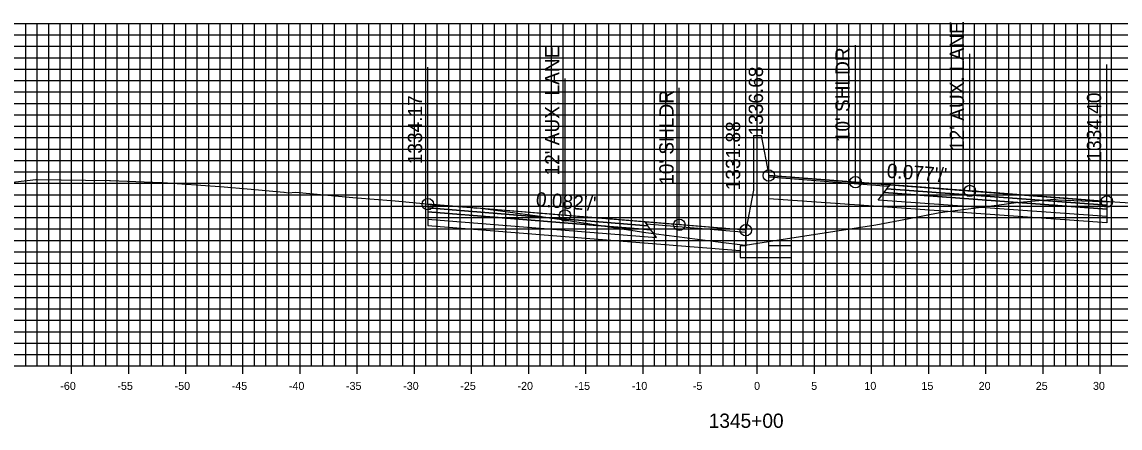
# Model space of a CAD drawing. Extents: x 674939 to 678919, y 750652 to 765176.
# Drawn here: x 678674.2 to 678770.3, y 753062.1 to 753097.7 of the extents above; entities that cross this region are included whole.
import ezdxf

# ---------------------------------------------------------------- set-up
doc = ezdxf.new("R2010")
doc.units = 0
for name, color, linetype in [('R_Alt Surface', 7, 'Continuous'), ('R_Axis', 7, 'Continuous'), ('R_Axis Annot', 7, 'Continuous'), ('R_Exist Surface', 7, 'Continuous'), ('R_Fin Surface', 7, 'Continuous'), ('R_Grid', 7, 'Continuous'), ('R_No Plot', 7, 'Continuous'), ('R_Proposed Road', 7, 'Continuous'), ('R_Xsect Elev', 7, 'Continuous'), ('R_Xsect Slope', 7, 'Continuous')]:
    doc.layers.add(name, color=color, linetype=linetype)

msp = doc.modelspace()

# ---------------------------------------------------------------- linework, layer by layer
at = {"layer": 'R_Alt Surface'}
for points in [[(678769.12, 753081.295), (678769.12, 753080.635), (678749.12, 753082.057), (678749.62, 753082.737)], [(678769.12, 753081.625), (678769.12, 753081.295), (678749.62, 753082.737), (678749.87, 753083.077)], [(678709.709, 753081.386), (678709.709, 753081.056), (678729.209, 753079.478), (678728.959, 753079.818)], [(678709.709, 753081.056), (678709.709, 753080.396), (678729.709, 753078.798), (678729.209, 753079.478)]]:
    msp.add_lwpolyline(points, close=True, dxfattribs=at)
for points in [[(678749.12, 753081.517), (678739.533, 753082.199)], [(678769.12, 753080.635), (678769.121, 753080.095), (678749.12, 753081.517)], [(678709.709, 753080.396), (678709.709, 753079.856), (678729.709, 753078.258)], [(678729.709, 753078.258), (678737.033, 753077.673)]]:
    msp.add_lwpolyline(points, dxfattribs=at)
at = {"layer": 'R_Axis'}
for p, q in [((678678.533, 753066.851), (678678.533, 753068.251)), ((678683.533, 753066.851), (678683.533, 753068.251)), ((678688.533, 753066.851), (678688.533, 753068.251)), ((678693.533, 753066.851), (678693.533, 753068.251)), ((678698.533, 753066.851), (678698.533, 753068.251)), ((678703.533, 753066.851), (678703.533, 753068.251)), ((678708.533, 753066.851), (678708.533, 753068.251)), ((678713.533, 753066.851), (678713.533, 753068.251)), ((678718.533, 753066.851), (678718.533, 753068.251)), ((678723.533, 753066.851), (678723.533, 753068.251)), ((678728.533, 753066.851), (678728.533, 753068.251)), ((678733.533, 753066.851), (678733.533, 753068.251)), ((678738.533, 753066.851), (678738.533, 753068.251)), ((678743.533, 753066.851), (678743.533, 753068.251)), ((678748.533, 753066.851), (678748.533, 753068.251)), ((678753.533, 753066.851), (678753.533, 753068.251)), ((678758.533, 753066.851), (678758.533, 753068.251)), ((678763.533, 753066.851), (678763.533, 753068.251)), ((678768.533, 753066.851), (678768.533, 753068.251)), ((678638.533, 753067.551), (678838.533, 753067.551))]:
    msp.add_line(p, q, dxfattribs=at)
at = {"layer": 'R_Exist Surface'}
msp.add_lwpolyline([(678671.826, 753083.464), (678675.401, 753083.866), (678675.405, 753083.866), (678675.531, 753083.889), (678681.853, 753083.782), (678681.941, 753083.78), (678686.361, 753083.629), (678686.385, 753083.628), (678686.388, 753083.628), (678686.528, 753083.623), (678691.513, 753083.259), (678691.533, 753083.257), (678694.246, 753083.023), (678697.12, 753082.775), (678697.127, 753082.774), (678697.526, 753082.726), (678697.529, 753082.726), (678698.127, 753082.758), (678703.476, 753082.287), (678703.53, 753082.282), (678706.492, 753082.053), (678706.549, 753082.048), (678709.31, 753081.772), (678709.331, 753081.769), (678709.709, 753081.716), (678709.719, 753081.715), (678710.129, 753081.657), (678710.145, 753081.656), (678711.522, 753081.589), (678711.536, 753081.588), (678711.558, 753081.586), (678713.521, 753081.423), (678713.529, 753081.422), (678713.537, 753081.423), (678713.929, 753081.381), (678714.102, 753081.391), (678719.311, 753080.687), (678720.158, 753080.566), (678721.432, 753080.385), (678728.77, 753079.23), (678735.104, 753078.424), (678737.458, 753078.123), (678740.612, 753078.616), (678748.891, 753079.903), (678751.665, 753080.424), (678754.489, 753080.979), (678759.688, 753081.672), (678761.175, 753081.869), (678761.818, 753081.933), (678764.548, 753082.16), (678764.632, 753082.143), (678764.865, 753082.099), (678765.532, 753082.077), (678766.931, 753082.025), (678767.851, 753081.978), (678768.433, 753081.942), (678768.871, 753081.949), (678769.12, 753081.955), (678769.262, 753081.958), (678769.349, 753081.96), (678771.62, 753081.795)], dxfattribs=at)
at = {"layer": 'R_Fin Surface'}
for points in [[(678769.12, 753081.955), (678757.12, 753082.878), (678747.12, 753083.648), (678739.533, 753084.232)], [(678737.533, 753079.435), (678731.709, 753079.913), (678721.709, 753080.732), (678709.709, 753081.716)]]:
    msp.add_lwpolyline(points, dxfattribs=at)
for points in [[(678750.002, 753083.257), (678739.533, 753084.072), (678739.533, 753084.232), (678750.12, 753083.417)], [(678769.12, 753081.955), (678769.12, 753081.625), (678749.87, 753083.077), (678750.12, 753083.417)], [(678709.709, 753081.716), (678709.709, 753081.386), (678728.959, 753079.818), (678728.709, 753080.158)], [(678728.827, 753079.998), (678737.533, 753079.275), (678737.533, 753079.435), (678728.709, 753080.158)]]:
    msp.add_lwpolyline(points, close=True, dxfattribs=at)
at = {"layer": 'R_Grid'}
for p, q in [((678638.533, 753097.551), (678838.533, 753097.551)), ((678674.533, 753067.551), (678674.533, 753097.551)), ((678675.533, 753067.551), (678675.533, 753097.551)), ((678676.533, 753067.551), (678676.533, 753097.551)), ((678677.533, 753067.551), (678677.533, 753097.551)), ((678678.533, 753067.551), (678678.533, 753097.551)), ((678679.533, 753067.551), (678679.533, 753097.551)), ((678680.533, 753067.551), (678680.533, 753097.551)), ((678681.533, 753067.551), (678681.533, 753097.551)), ((678682.533, 753067.551), (678682.533, 753097.551)), ((678683.533, 753067.551), (678683.533, 753097.551)), ((678684.533, 753067.551), (678684.533, 753097.551)), ((678685.533, 753067.551), (678685.533, 753097.551)), ((678686.533, 753067.551), (678686.533, 753097.551)), ((678687.533, 753067.551), (678687.533, 753097.551)), ((678688.533, 753067.551), (678688.533, 753097.551)), ((678689.533, 753067.551), (678689.533, 753097.551)), ((678690.533, 753067.551), (678690.533, 753097.551)), ((678691.533, 753067.551), (678691.533, 753097.551)), ((678692.533, 753067.551), (678692.533, 753097.551)), ((678693.533, 753067.551), (678693.533, 753097.551)), ((678694.533, 753067.551), (678694.533, 753097.551)), ((678695.533, 753067.551), (678695.533, 753097.551)), ((678696.533, 753067.551), (678696.533, 753097.551)), ((678697.533, 753067.551), (678697.533, 753097.551)), ((678698.533, 753067.551), (678698.533, 753097.551)), ((678699.533, 753067.551), (678699.533, 753097.551)), ((678700.533, 753067.551), (678700.533, 753097.551)), ((678701.533, 753067.551), (678701.533, 753097.551)), ((678702.533, 753067.551), (678702.533, 753097.551)), ((678703.533, 753067.551), (678703.533, 753097.551)), ((678704.533, 753067.551), (678704.533, 753097.551)), ((678705.533, 753067.551), (678705.533, 753097.551)), ((678706.533, 753067.551), (678706.533, 753097.551)), ((678707.533, 753067.551), (678707.533, 753097.551)), ((678708.533, 753067.551), (678708.533, 753097.551)), ((678709.533, 753067.551), (678709.533, 753097.551)), ((678710.533, 753067.551), (678710.533, 753097.551)), ((678711.533, 753067.551), (678711.533, 753097.551)), ((678712.533, 753067.551), (678712.533, 753097.551)), ((678713.533, 753067.551), (678713.533, 753097.551)), ((678714.533, 753067.551), (678714.533, 753097.551)), ((678715.533, 753067.551), (678715.533, 753097.551)), ((678716.533, 753067.551), (678716.533, 753097.551)), ((678717.533, 753067.551), (678717.533, 753097.551)), ((678718.533, 753067.551), (678718.533, 753097.551)), ((678719.533, 753067.551), (678719.533, 753097.551)), ((678720.533, 753067.551), (678720.533, 753097.551)), ((678721.533, 753067.551), (678721.533, 753097.551)), ((678722.533, 753067.551), (678722.533, 753097.551)), ((678723.533, 753067.551), (678723.533, 753097.551)), ((678724.533, 753067.551), (678724.533, 753097.551)), ((678725.533, 753067.551), (678725.533, 753097.551)), ((678726.533, 753067.551), (678726.533, 753097.551)), ((678727.533, 753067.551), (678727.533, 753097.551)), ((678728.533, 753067.551), (678728.533, 753097.551)), ((678729.533, 753067.551), (678729.533, 753097.551)), ((678730.533, 753067.551), (678730.533, 753097.551)), ((678731.533, 753067.551), (678731.533, 753097.551)), ((678732.533, 753067.551), (678732.533, 753097.551)), ((678733.533, 753067.551), (678733.533, 753097.551)), ((678734.533, 753067.551), (678734.533, 753097.551)), ((678735.533, 753067.551), (678735.533, 753097.551)), ((678736.533, 753067.551), (678736.533, 753097.551)), ((678737.533, 753067.551), (678737.533, 753097.551)), ((678738.533, 753067.551), (678738.533, 753097.551)), ((678739.533, 753067.551), (678739.533, 753097.551)), ((678740.533, 753067.551), (678740.533, 753097.551)), ((678741.533, 753067.551), (678741.533, 753097.551)), ((678742.533, 753067.551), (678742.533, 753097.551)), ((678743.533, 753067.551), (678743.533, 753097.551)), ((678744.533, 753067.551), (678744.533, 753097.551)), ((678745.533, 753067.551), (678745.533, 753097.551)), ((678746.533, 753067.551), (678746.533, 753097.551)), ((678747.533, 753067.551), (678747.533, 753097.551)), ((678748.533, 753067.551), (678748.533, 753097.551)), ((678749.533, 753067.551), (678749.533, 753097.551)), ((678750.533, 753067.551), (678750.533, 753097.551)), ((678751.533, 753067.551), (678751.533, 753097.551)), ((678752.533, 753067.551), (678752.533, 753097.551)), ((678753.533, 753067.551), (678753.533, 753097.551)), ((678754.533, 753067.551), (678754.533, 753097.551)), ((678755.533, 753067.551), (678755.533, 753097.551)), ((678756.533, 753067.551), (678756.533, 753097.551)), ((678757.533, 753067.551), (678757.533, 753097.551)), ((678758.533, 753067.551), (678758.533, 753097.551)), ((678759.533, 753067.551), (678759.533, 753097.551)), ((678760.533, 753067.551), (678760.533, 753097.551)), ((678761.533, 753067.551), (678761.533, 753097.551)), ((678762.533, 753067.551), (678762.533, 753097.551)), ((678763.533, 753067.551), (678763.533, 753097.551)), ((678764.533, 753067.551), (678764.533, 753097.551)), ((678765.533, 753067.551), (678765.533, 753097.551)), ((678766.533, 753067.551), (678766.533, 753097.551)), ((678767.533, 753067.551), (678767.533, 753097.551)), ((678768.533, 753067.551), (678768.533, 753097.551)), ((678769.533, 753067.551), (678769.533, 753097.551)), ((678638.533, 753096.551), (678838.533, 753096.551)), ((678638.533, 753095.551), (678838.533, 753095.551)), ((678638.533, 753094.551), (678838.533, 753094.551)), ((678638.533, 753093.551), (678838.533, 753093.551)), ((678638.533, 753092.551), (678838.533, 753092.551)), ((678638.533, 753091.551), (678838.533, 753091.551)), ((678638.533, 753090.551), (678838.533, 753090.551)), ((678638.533, 753089.551), (678838.533, 753089.551)), ((678638.533, 753088.551), (678838.533, 753088.551)), ((678638.533, 753087.551), (678838.533, 753087.551)), ((678638.533, 753086.551), (678838.533, 753086.551)), ((678638.533, 753085.551), (678838.533, 753085.551)), ((678638.533, 753084.551), (678838.533, 753084.551)), ((678638.533, 753083.551), (678838.533, 753083.551)), ((678638.533, 753082.551), (678838.533, 753082.551)), ((678638.533, 753081.551), (678838.533, 753081.551)), ((678638.533, 753080.551), (678838.533, 753080.551)), ((678638.533, 753079.551), (678838.533, 753079.551)), ((678638.533, 753078.551), (678838.533, 753078.551)), ((678638.533, 753077.551), (678838.533, 753077.551)), ((678638.533, 753076.551), (678838.533, 753076.551)), ((678638.533, 753075.551), (678838.533, 753075.551)), ((678638.533, 753074.551), (678838.533, 753074.551)), ((678638.533, 753073.551), (678838.533, 753073.551)), ((678638.533, 753072.551), (678838.533, 753072.551)), ((678638.533, 753071.551), (678838.533, 753071.551)), ((678638.533, 753070.551), (678838.533, 753070.551)), ((678638.533, 753069.551), (678838.533, 753069.551)), ((678638.533, 753068.551), (678838.533, 753068.551)), ((678638.533, 753067.551), (678838.533, 753067.551))]:
    msp.add_line(p, q, dxfattribs=at)
at = {"layer": 'R_No Plot'}
for centre in [(678739.533, 753084.232), (678747.12, 753083.648), (678757.12, 753082.878), (678769.12, 753081.955), (678709.709, 753081.716), (678721.709, 753080.732), (678731.709, 753079.913), (678737.533, 753079.435)]:
    msp.add_circle(centre, 0.5, dxfattribs=at)
at = {"layer": 'R_Proposed Road'}
for points in [[(678738.203, 753087.732), (678738.203, 753082.935)], [(678738.203, 753087.732), (678738.863, 753087.732)], [(678738.863, 753087.732), (678739.533, 753084.232)], [(678738.863, 753087.732), (678738.863, 753087.732)], [(678737.533, 753079.435), (678737.533, 753078.06), (678737.033, 753078.06), (678737.033, 753077.06), (678741.533, 753077.06), (678741.533, 753078.06), (678739.533, 753078.06), (678739.533, 753084.232)], [(678738.203, 753082.935), (678737.533, 753079.435)]]:
    msp.add_lwpolyline(points, dxfattribs=at)
at = {"layer": 'R_Xsect Elev'}
for p, q in [((678739.533, 753084.232), (678739.533, 753096.232)), ((678747.12, 753083.648), (678747.12, 753095.648)), ((678757.12, 753082.878), (678757.12, 753094.878)), ((678709.709, 753081.716), (678709.709, 753093.716)), ((678769.12, 753081.955), (678769.12, 753093.955)), ((678721.709, 753080.732), (678721.709, 753092.732)), ((678731.709, 753079.913), (678731.709, 753091.913)), ((678737.533, 753079.435), (678737.533, 753091.435))]:
    msp.add_line(p, q, dxfattribs=at)

# ---------------------------------------------------------------- texts
at = {"layer": 'R_Axis Annot'}
for s, height, p in [('-60', 0.7, (678677.552, 753065.451)), ('-55', 0.7, (678682.546, 753065.451)), ('-50', 0.7, (678687.552, 753065.451)), ('-45', 0.7, (678692.546, 753065.451)), ('-40', 0.7, (678697.552, 753065.451)), ('-35', 0.7, (678702.546, 753065.451)), ('-30', 0.7, (678707.552, 753065.451)), ('-25', 0.7, (678712.546, 753065.451)), ('-20', 0.7, (678717.552, 753065.451)), ('-15', 0.7, (678722.546, 753065.451)), ('-10', 0.7, (678727.552, 753065.451)), ('-5', 0.7, (678732.896, 753065.451)), ('0', 0.7, (678738.252, 753065.451)), ('5', 0.7, (678743.246, 753065.451)), ('10', 0.7, (678747.902, 753065.451)), ('15', 0.7, (678752.896, 753065.451)), ('20', 0.7, (678757.902, 753065.451)), ('25', 0.7, (678762.896, 753065.451)), ('30', 0.7, (678767.902, 753065.451)), ('1345+00', 1.25, (678734.281, 753062.126))]:
    msp.add_text(s, height=height, dxfattribs=at).set_placement(p)
at = {"layer": 'R_Xsect Elev'}
for s, p in [("12' AUX. LANE", (678756.62, 753086.378)), ("12' AUX. LANE", (678721.209, 753084.232)), ("10' SHLDR", (678746.62, 753087.148)), ('1336.68', (678739.033, 753087.732)), ('1334.17', (678709.209, 753085.216)), ("10' SHLDR", (678731.209, 753083.413)), ('1334.40', (678768.62, 753085.455)), ('1331.88', (678737.033, 753082.935))]:
    msp.add_text(s, height=1.25, rotation=90, dxfattribs=at).set_placement(p)
at = {"layer": 'R_Xsect Slope'}
for s, rotation, p in [("0.077'/'", 355.59912, (678749.823, 753084.042)), ("0.082'/'", 355.31329, (678719.122, 753081.546))]:
    msp.add_text(s, height=1.25, rotation=rotation, dxfattribs=at).set_placement(p)

doc.saveas('drawing.dxf')
